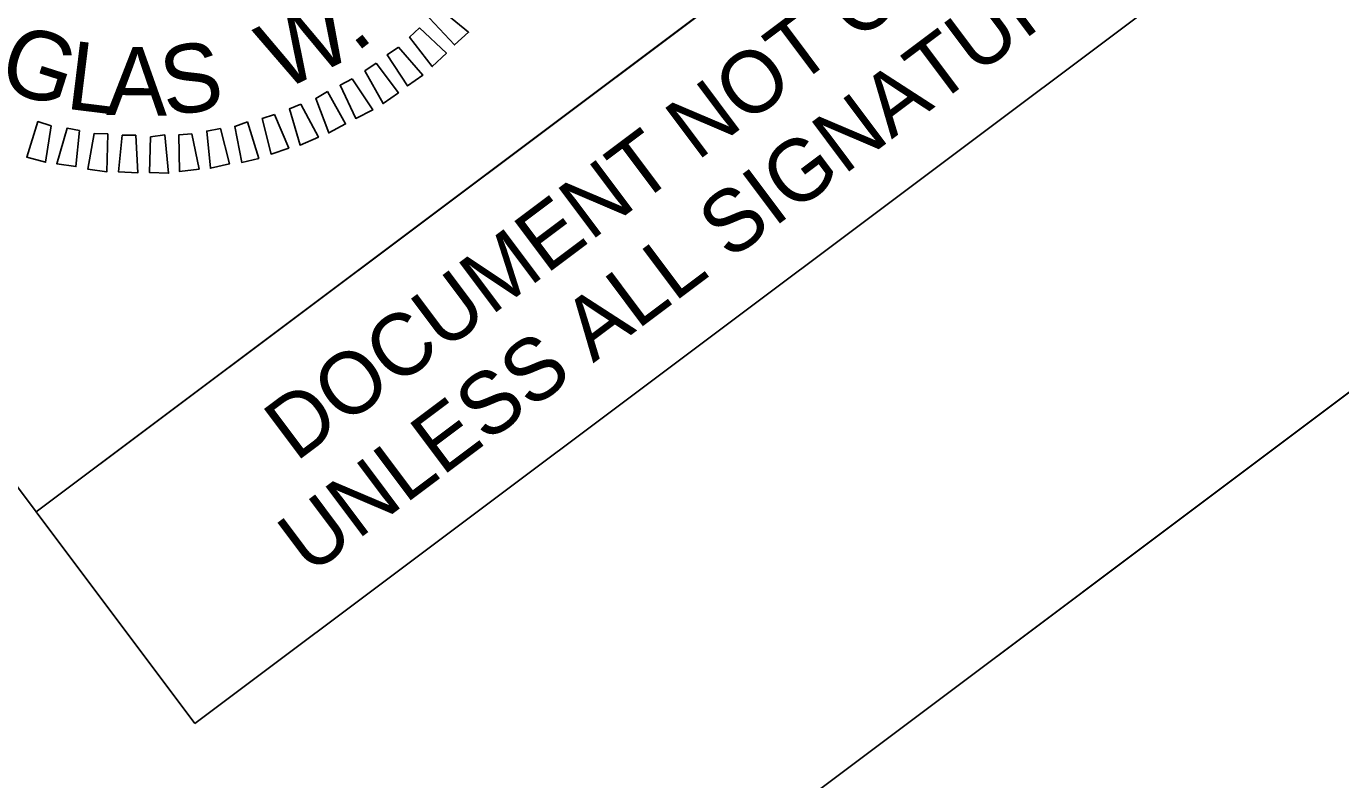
# Model space of a CAD drawing. Extents: x 2186558 to 2188589, y 629855 to 631741.
# Drawn here: x 2187861 to 2187977.7, y 631449 to 631515.8 of the extents above; entities that cross this region are included whole.
import ezdxf

# ---------------------------------------------------------------- set-up
doc = ezdxf.new("R2010")
doc.units = 0
for name, color, linetype in [('Sheet PE Seal Cell', 7, 'Continuous'), ('Sheet Plan CELL', 7, 'Continuous'), ('Sheet Plan Layout CELL', 7, 'Continuous'), ('Sheet Sticker Exception Certification CELL', 7, 'Continuous')]:
    doc.layers.add(name, color=color, linetype=linetype)

msp = doc.modelspace()

# ---------------------------------------------------------------- linework, layer by layer
at = {"layer": 'Sheet PE Seal Cell'}
for points in [[(2187897.65, 631517.41), (2187900.24, 631515.31), (2187898.99, 631514.18), (2187896.76, 631516.56)], [(2187895.88, 631515.71), (2187898.27, 631513.45), (2187897.02, 631512.26), (2187895, 631514.86)], [(2187894.01, 631513.99), (2187896.19, 631511.51), (2187894.82, 631510.55), (2187893.01, 631513.3)], [(2187892.04, 631512.57), (2187894.01, 631509.94), (2187892.65, 631508.98), (2187891.04, 631511.88)], [(2187889.92, 631511.17), (2187891.73, 631508.42), (2187890.22, 631507.66), (2187888.83, 631510.6)], [(2187887.73, 631510.04), (2187889.32, 631507.17), (2187887.83, 631506.37), (2187886.67, 631509.43)], [(2187885.34, 631508.93), (2187886.91, 631506), (2187885.29, 631505.29), (2187884.33, 631508.5)], [(2187863.18, 631506.99), (2187862.69, 631503.77), (2187861.02, 631504.23), (2187862.01, 631507.38)], [(2187880.63, 631507.36), (2187881.61, 631504.11), (2187880.11, 631503.75), (2187879.48, 631506.95)], [(2187883, 631508), (2187884.27, 631505.03), (2187882.71, 631504.5), (2187881.93, 631507.65)], [(2187865.69, 631506.6), (2187865.38, 631503.39), (2187863.68, 631503.63), (2187864.6, 631506.79)], [(2187868.21, 631506.28), (2187868.13, 631502.93), (2187866.43, 631503.17), (2187866.99, 631506.31)], [(2187870.7, 631506.18), (2187870.87, 631502.82), (2187869.15, 631502.93), (2187869.5, 631506.17)], [(2187873.27, 631506.21), (2187873.61, 631502.79), (2187871.92, 631502.86), (2187872.01, 631506.02)], [(2187875.67, 631506.3), (2187876.31, 631503.17), (2187874.57, 631502.95), (2187874.53, 631506.21)], [(2187878.23, 631506.76), (2187879.01, 631503.62), (2187877.33, 631503.24), (2187877, 631506.54)]]:
    msp.add_lwpolyline(points, close=True, dxfattribs=at)
at = {"layer": 'Sheet Plan CELL'}
for points in [[(2187794.35, 631562.75), (2187874.4, 631622.77), (2187941.9, 631532.75), (2187861.84, 631472.76)], [(2187361.55, 629972.91), (2186731.7, 630812.99), (2187771.81, 631592.82), (2187861.84, 631472.76), (2188021.9, 631592.74), (2188561.73, 630872.69)]]:
    msp.add_lwpolyline(points, close=True, dxfattribs=at)
at = {"layer": 'Sheet Plan Layout CELL'}
for points in [[(2187867.31, 631400.07), (2188058.75, 631543.6), (2187931.91, 631712.83), (2187740.45, 631569.29)], [(2186731.7, 630812.99), (2187361.55, 629972.91), (2188561.72, 630872.68), (2188058.73, 631543.59), (2187867.31, 631400.07), (2187740.45, 631569.29)]]:
    msp.add_lwpolyline(points, close=True, dxfattribs=at)
at = {"layer": 'Sheet Sticker Exception Certification CELL'}
for p, q in [((2187861.84, 631472.76), (2188021.89, 631592.75)), ((2187861.84, 631472.76), (2188021.89, 631592.75)), ((2188035.99, 631573.95), (2187875.94, 631453.96)), ((2188035.99, 631573.95), (2187875.94, 631453.96)), ((2187875.94, 631453.96), (2187861.84, 631472.76)), ((2187875.94, 631453.96), (2187861.84, 631472.76))]:
    msp.add_line(p, q, dxfattribs=at)

# ---------------------------------------------------------------- texts
at = {"layer": 'Sheet PE Seal Cell'}
for s, rotation, p in [('W', 25.6394, (2187883.55, 631510.01)), ('G', 342.2724, (2187858.25, 631510.44)), ('L', 352.9982, (2187864.36, 631508.54)), ('S', 8.1133, (2187873.34, 631507.85)), ('.', 38.1734, (2187890.21, 631513.41)), ('A', 359.273, (2187868.06, 631507.97))]:
    msp.add_text(s, height=6.07, rotation=rotation, dxfattribs=at).set_placement(p)
at = {"layer": 'Sheet Sticker Exception Certification CELL'}
for s, p in [('DOCUMENT NOT CONSIDERED FINAL', (2187884.9, 631477.12)), ('DOCUMENT NOT CONSIDERED FINAL', (2187884.9, 631477.12)), ('UNLESS ALL SIGNATURES COMPLETED', (2187886.12, 631467.04)), ('UNLESS ALL SIGNATURES COMPLETED', (2187886.12, 631467.04))]:
    msp.add_text(s, height=5.5, rotation=36.8593, dxfattribs=at).set_placement(p)

doc.saveas('drawing.dxf')
